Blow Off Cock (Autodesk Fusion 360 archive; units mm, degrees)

design "Blow Off Cock" references "Stud", "Cock", "Nut", "Gland", "Body"
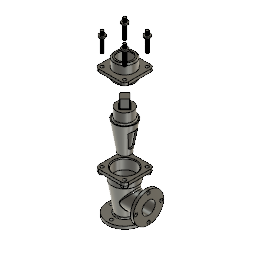
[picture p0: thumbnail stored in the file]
component_insert "Component Insert1"
ground "Ground1"
component_insert "Component Insert2"
joint "Assemble1" OffsetX 0 OffsetY 0 OffsetZ 0 AngleZ 0 OffsetX 0 OffsetY 0 OffsetZ 0 AngleZ 0 alignAngle 0 alignOffsetX 0 alignOffsetY 0 alignOffsetZ 0
component_insert "Component Insert3"
joint "Assemble2" OffsetX 0 OffsetY 0 OffsetZ 0 AngleZ 0 OffsetX 0 OffsetY 0 OffsetZ 0 AngleZ 0 alignAngle 0 alignOffsetX 0 alignOffsetY 0 alignOffsetZ 0
component_insert "Component Insert4"
joint "Assemble3" OffsetX 0 OffsetY 0 OffsetZ 0 AngleZ 0 OffsetX 0 OffsetY 0 OffsetZ 0 AngleZ 0 alignAngle 0 alignOffsetX 0 alignOffsetY 0 alignOffsetZ 0
component_insert "Component Insert5"
joint "Assemble4" OffsetX 0 OffsetY 0 OffsetZ 0 AngleZ 0 OffsetX 0 OffsetY 0 OffsetZ 0 AngleZ 0 alignAngle 0 alignOffsetX 0 alignOffsetY 0 alignOffsetZ 0
component_insert "Component Insert6"
joint "Assemble5" OffsetX 0 OffsetY 0 OffsetZ 0 AngleZ 0 OffsetX 0 OffsetY 0 OffsetZ 0 AngleZ 0 alignAngle 0 alignOffsetX 0 alignOffsetY 0 alignOffsetZ 0
component_insert "Component Insert7"
joint "Assemble6" OffsetX 0 OffsetY 0 OffsetZ 0 AngleZ 0 OffsetX 0 OffsetY 0 OffsetZ 0 AngleZ 0 alignAngle 0 alignOffsetX 0 alignOffsetY 0 alignOffsetZ 0
component_insert "Component Insert8"
joint "Assemble7" OffsetX 0 OffsetY 0 OffsetZ 0 AngleZ 0 OffsetX 0 OffsetY 0 OffsetZ 0 AngleZ 0 alignAngle 0 alignOffsetX 0 alignOffsetY 0 alignOffsetZ 0
component_insert "Component Insert9"
joint "Assemble8" OffsetX 0 OffsetY 0 OffsetZ 0 AngleZ 0 OffsetX 0 OffsetY 0 OffsetZ 0 AngleZ 0 alignAngle 0 alignOffsetX 0 alignOffsetY 0 alignOffsetZ 0
component_insert "Component Insert10"
joint "Assemble9" OffsetX 0 OffsetY 0 OffsetZ 0 AngleZ 0 OffsetX 0 OffsetY 0 OffsetZ 0 AngleZ 0 alignAngle 0 alignOffsetX 0 alignOffsetY 0 alignOffsetZ 0
component_insert "Component Insert11"
joint "Assemble10" OffsetX 0 OffsetY 0 OffsetZ 0 AngleZ 0 OffsetX 0 OffsetY 0 OffsetZ 0 AngleZ 0 alignAngle 0 alignOffsetX 0 alignOffsetY 0 alignOffsetZ 0

design "Nut"
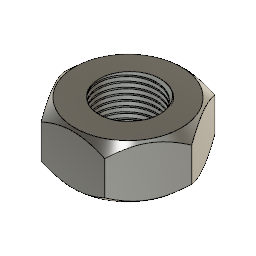
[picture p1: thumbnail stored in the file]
sketch "Sketch1" plane through (0, 0, 0) normal (0, 0, 1) x axis (1, 0, 0)
  line L1 (-12, 0) -> (-6, 10.3923)
  line L2 (-6, -10.3923) -> (-12, 0)
  line L3 (6, -10.3923) -> (-6, -10.3923)
  line L4 (12, 0) -> (6, -10.3923)
  line L5 (6, 10.3923) -> (12, 0)
  line L6 (-6, 10.3923) -> (6, 10.3923)
  circle C1 centre (0, 0) radius 6
  point P1 (0, 0)
  point P2 (0, 0)
  point P9 (0, 0)
  point P4 (-12, 0)
  point P7 (12, 0)
  point P3 (-6, 10.3923)
  point P8 (6, 10.3923)
  coincident P1 P2
  coincident P2 P9
  horizontal P4 P7
  dimension "d1" diameter C1 = 12
  dimension "d2" distance P3 P8 = 12
extrude "Extrude1" new body sketch "Sketch1" distance 10
sketch "Sketch2" plane through (0, 0, 5) normal (0, 0, 1) x axis (-1, 0, 0)
  line L1 (6, -10.3923) -> (-6, -10.3923)
  line L2 (12, 0) -> (6, -10.3923)
  line L3 (6, 10.3923) -> (12, 0)
  line L4 (-6, 10.3923) -> (6, 10.3923)
  line L5 (-12, 0) -> (-6, 10.3923)
  line L6 (-6, -10.3923) -> (-12, 0)
  circle C1 centre (0, 0) radius 6
  circle C2 centre (0, 0) radius 10
  point P1 (0, 0)
  point P9 (0, 0)
  coincident P1 P9
  dimension "d5" diameter C2 = 20
extrude "Extrude2" sketch "Sketch2" profile of C1 C2 no distance stored taper 48
mirror "Mirror1"
thread "Thread1"

design "Cock"
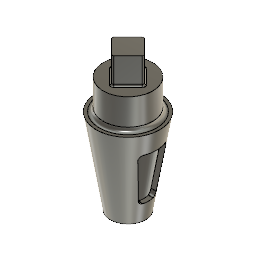
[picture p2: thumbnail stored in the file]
sketch "Sketch1" plane through (0, 0, 0) normal (0, 1, 0) x axis (1, 0, 0)
  line L1 (23, 0) -> (17, 0)
  line L2 (41, -110) -> (23, 0)
  line L3 (0, -144.3099) -> (0, 0)
  line L4 (17, 0) -> (34.0182, -104)
  line L5 (37.7698, 0) -> (0, 0)
  line L6 (32, -110) -> (41, -110)
  line L7 (32, -149) -> (32, -110)
  line L8 (26, -104) -> (34.0182, -104)
  line L9 (26, -143) -> (26, -104)
  line L10 (0, -149) -> (32, -149)
  line L11 (0, -143) -> (26, -143)
  line L12 (0, -143) -> (0, -149)
  point P1 (0, 0)
  point P4 (0, 0)
  point P8 (0, 0)
  point P7 (17, 0)
  point P14 (0, -149)
  point P15 (0, -143)
  point P3 (41, -110)
  horizontal L1
  coincident P1 P4
  perpendicular L1 L3
  parallel L2 L4
  coincident P1 P8
  perpendicular L3 L5
  horizontal P1 P7
  horizontal L6
  perpendicular L6 L7
  horizontal L8
  perpendicular L8 L9
  perpendicular L7 L10
  coincident L3 P14
  coincident L3 P15
  perpendicular L3 L11
  dimension "d1" = 46
  dimension "d2" = 34
  dimension "d3" distance L1 P3 = 110
  dimension "d4" = 82
  dimension "d5" distance L6 L8 = 6
  dimension "d7" = 64
  dimension "d8" distance L7 L9 = 6
  dimension "d9" distance L5 L10 = 149
  dimension "d10" distance L10 L11 = 6
revolve "Revolve1" sketch "Sketch1" AlongAngle 360
sketch "Sketch2" plane through (0, 0, 149) normal (0, 0, 1) x axis (-1, 0, 0)
  line L1 (21.2132, 0) -> (0, -21.2132)
  line L2 (0, 21.2132) -> (21.2132, 0)
  line L3 (-21.2132, 0) -> (0, 21.2132)
  line L4 (0, -21.2132) -> (-21.2132, 0)
  point P1 (0, 0)
  point P3 (21.2132, 0)
  point P5 (-21.2132, 0)
  point P2 (0, -21.2132)
  point P4 (0, 21.2132)
  perpendicular L2 L3
  horizontal P1 P3
  horizontal P1 P5
  vertical P1 P2
  vertical P1 P4
  equal L1 L2
  equal L1 L4
  dimension "d28" distance P2 P5 = 30
extrude "Extrude1" add sketch "Sketch2" along normal blind 34
fillet "Fillet1" radius 2
fillet "Fillet2" radius 2
fillet "Fillet3" radius 5
fillet "Fillet4" radius 5
sketch "Sketch5" plane through (0, 0, 0) normal (1, 0, 0) x axis (0, 1, 0)
  line L1 (-23, 0) -> (23, 0)
  line L2 (0, 97.021) -> (0, 0)
  line L3 (13.3134, 85) -> (-13.3134, 85)
  line L4 (11.5626, 27.3601) -> (18.2723, 79.3601)
  line L5 (-6.6037, 23) -> (6.6037, 23)
  line L6 (-18.2723, 79.3601) -> (-11.5626, 27.3601)
  line L7 (-41, 110) -> (41, 110)
  arc A1 centre (-13.3134, 80) radius 5 clockwise from (-18.2723, 79.3601) to (-13.3134, 85)
  arc A2 centre (13.3134, 80) radius 5 clockwise from (13.3134, 85) to (18.2723, 79.3601)
  arc A3 centre (6.6037, 28) radius 5 clockwise from (11.5626, 27.3601) to (6.6037, 23)
  arc A4 centre (-6.6037, 28) radius 5 clockwise from (-6.6037, 23) to (-11.5626, 27.3601)
  point P1 (0, 0)
  point P4 (0, 0)
  point P6 (-19, 85)
  point P7 (19, 85)
  point P8 (11, 23)
  point P9 (-11, 23)
  coincident P1 P4
  perpendicular L1 L2
  perpendicular L2 L3
  perpendicular L2 L5
  symmetric L2 P6 P7
  symmetric L2 P8 P9
  coincident P6 L6
  tangent L3 A1
  tangent L6 A1
  coincident P7 L4
  coincident P7 L3
  tangent L4 A2
  tangent L3 A2
  equal A1 A2
  coincident P8 L4
  tangent L4 A3
  tangent L5 A3
  equal A1 A3
  coincident P9 L5
  coincident P9 L6
  tangent L5 A4
  tangent L6 A4
  equal A1 A4
  dimension "d36" distance L3 L5 = 62
  dimension "d37" distance L3 L7 = 25
  dimension "d38" distance P6 P7 = 38
  dimension "d39" distance P8 P9 = 22
  dimension "d40" radius A1 = 5
extrude "Extrude4" cut sketch "Sketch5" profile of L3 L4 L5 L6 A1 A2 A3 A4 no distance stored
sketch "Sketch4" plane through (0, 0, 143) normal (0, 0, -1) x axis (1, 0, 0)
  circle C1 centre (0, 0) radius 26
  circle C2 centre (0, 0) radius 12
  point P1 (0, 0)
  point P3 (0, 0)
  coincident P1 P3
  dimension "d31" diameter C2 = 24
extrude "Extrude3" cut sketch "Sketch4" profile of C2 against normal blind 32
fillet "Fillet5" radius 5
fillet "Fillet6" radius 5

design "Gland"
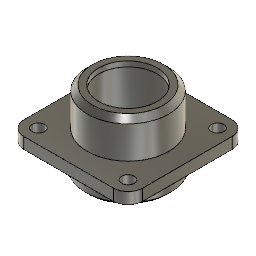
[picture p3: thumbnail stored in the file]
sketch "Sketch1" plane through (0, 0, 0) normal (0, 0, 1) x axis (1, 0, 0)
  circle C1 centre (0, 0) radius 41
  point P1 (0, 0)
  point P2 (0, 0)
  coincident P1 P2
  dimension "d1" diameter C1 = 82
extrude "Extrude1" new body sketch "Sketch1" along normal blind 25
sketch "Sketch2" plane through (0, 0, 25) normal (0, 0, 1) x axis (-1, 0, 0)
  line L1 (57, -57) -> (-57, -57)
  line L2 (57, 57) -> (57, -57)
  line L3 (-57, 57) -> (57, 57)
  line L4 (-57, -57) -> (-57, 57)
  line L5 (57, 57) -> (-57, -57)
  line L6 (-57, 57) -> (57, -57)
  circle C1 centre (0, 0) radius 41
  point P7 (0, 0)
  point P1 (0, 0)
  point P3 (-57, -57)
  point P4 (57, -57)
  point P5 (57, 57)
  horizontal L1
  perpendicular L1 L2
  parallel L1 L3
  parallel L2 L4
  coincident L5 P7
  coincident L6 P7
  coincident P1 P7
  dimension "d4" distance P3 P4 = 114
  dimension "d5" distance P4 P5 = 114
extrude "Extrude2" add sketch "Sketch2" profile of C1 L1 L2 L3 L4 along normal blind 11
fillet "Fillet1" sketch "Sketch5" radius 14
sketch "Sketch3" plane through (0, 0, 36) normal (0, 0, 1) x axis (-1, 0, 0)
  line L1 (43, -57) -> (-43, -57)
  line L2 (57, 43) -> (57, -43)
  line L3 (-43, 57) -> (43, 57)
  line L4 (-57, -43) -> (-57, 43)
  arc A1 centre (-43, -43) radius 14 clockwise from (-43, -57) to (-57, -43)
  arc A2 centre (43, -43) radius 14 clockwise from (57, -43) to (43, -57)
  arc A3 centre (43, 43) radius 14 clockwise from (43, 57) to (57, 43)
  arc A4 centre (-43, 43) radius 14 clockwise from (-57, 43) to (-43, 57)
  circle C1 centre (0, 0) radius 39
  point P1 (0, 0)
  point P14 (0, 0)
  coincident P1 P14
  dimension "d9" diameter C1 = 78
extrude "Extrude3" add sketch "Sketch3" profile of C1 along normal blind 36
chamfer "Chamfer1" distance 5 rotateAngle 45
sketch "Sketch4" plane through (0, 0, 0) normal (0, 1, 0) x axis (1, 0, 0)
  line L1 (-34, -72) -> (34, -72)
  line L2 (0, -90.6958) -> (0, 0)
  line L3 (-28, -72) -> (0, -72)
  line L4 (-28, -67) -> (-28, -72)
  line L5 (39, -67) -> (-39, -67)
  line L6 (-34, -67) -> (-28, -67)
  line L7 (-34, -21) -> (-34, -67)
  line L8 (-32, -21) -> (-34, -21)
  line L9 (41, 0) -> (-41, 0)
  line L10 (-32, 0) -> (-32, -21)
  line L11 (0, 0) -> (-32, 0)
  line L12 (0, -72) -> (0, 0)
  point P1 (0, 0)
  point P4 (0, 0)
  point P6 (0, -72)
  point P11 (-34, -67)
  point P16 (-32, 0)
  point P7 (-28, -72)
  point P17 (0, 0)
  point P18 (0, 0)
  point P8 (-28, -67)
  point P13 (-32, -21)
  coincident P1 P4
  perpendicular L1 L2
  coincident L2 P6
  perpendicular L2 L3
  perpendicular L3 L4
  coincident L5 P11
  perpendicular L4 L6
  perpendicular L5 L7
  perpendicular L7 L8
  coincident L9 P16
  perpendicular L5 L10
  coincident L1 P7
  coincident P1 P17
  coincident P1 P18
  dimension "d15" distance L2 L4 = 28
  dimension "d16" distance L1 P8 = 5
  dimension "d17" distance L2 L7 = 34
  dimension "d18" distance L2 L10 = 32
  dimension "d19" distance P13 P16 = 21
revolve "Revolve1" sketch "Sketch4" AlongAngle 360
sketch "Sketch5" plane through (0, 0, 36) normal (0, 0, 1) x axis (-1, 0, 0)
  line L1 (43, -57) -> (-43, -57)
  line L2 (57, 43) -> (57, -43)
  line L3 (-43, 57) -> (43, 57)
  line L4 (-57, -43) -> (-57, 43)
  circle C1 centre (0, 0) radius 39
  arc A1 centre (-43, -43) radius 14 clockwise from (-43, -57) to (-57, -43)
  arc A2 centre (43, -43) radius 14 clockwise from (57, -43) to (43, -57)
  arc A3 centre (43, 43) radius 14 clockwise from (43, 57) to (57, 43)
  arc A4 centre (-43, 43) radius 14 clockwise from (-57, 43) to (-43, 57)
  circle C2 centre (43, 43) radius 6
  concentric A3 C2
  dimension "d26" diameter C2 = 12
extrude "Extrude4" cut sketch "Sketch5" profile of C2 to an object
rectangular_pattern "R-Pattern1" uSpaceDistance 86 vSpaceDistance 86
chamfer "Chamfer2" distance 3 rotateAngle 45

design "Stud"
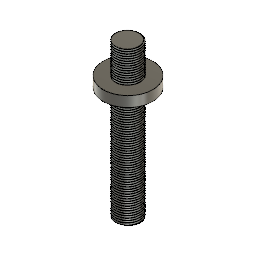
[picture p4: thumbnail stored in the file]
sketch "Sketch1" plane through (0, 0, 0) normal (0, 0, 1) x axis (1, 0, 0)
  circle C1 centre (0, 0) radius 6
  point P1 (0, 0)
  point P2 (0, 0)
  coincident P1 P2
  dimension "d1" diameter C1 = 12
extrude "Extrude1" new body sketch "Sketch1" along normal blind 54
sketch "Sketch2" plane through (0, 0, 54) normal (0, 0, 1) x axis (-1, 0, 0)
  circle C1 centre (0, 0) radius 6
  circle C2 centre (0, 0) radius 12
  point P1 (0, 0)
  point P3 (0, 0)
  coincident P1 P3
  dimension "d4" diameter C2 = 24
extrude "Extrude2" add sketch "Sketch2" along normal blind 5
sketch "Sketch3" plane through (0, 0, 59) normal (0, 0, 1) x axis (-1, 0, 0)
  circle C1 centre (0, 0) radius 12
  circle C2 centre (0, 0) radius 6
  point P1 (0, 0)
  point P3 (0, 0)
  coincident P1 P3
  dimension "d7" diameter C2 = 12
extrude "Extrude3" add sketch "Sketch3" profile of C2 along normal blind 15
thread "Thread1"
thread "Thread2"

design "Body"
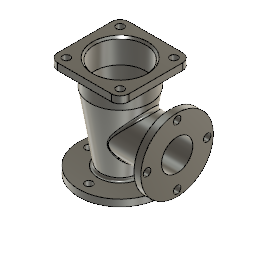
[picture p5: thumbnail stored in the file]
sketch "Sketch1" plane through (0, 0, 0) normal (0, 1, 0) x axis (1, 0, 0)
  line L1 (0, -187.0761) -> (0, 0)
  line L2 (30, -22) -> (30, 0)
  line L3 (17.5, 0) -> (30, 0)
  line L4 (17.5, -33) -> (17.5, 0)
  line L5 (66, -22) -> (30, -22)
  line L6 (66, -33) -> (66, -22)
  line L7 (30, -33) -> (66, -33)
  line L8 (48, -143) -> (30, -33)
  line L9 (48, -171) -> (48, -143)
  line L10 (41, -171) -> (48, -171)
  line L11 (41, -143) -> (41, -171)
  line L12 (23, -33) -> (41, -143)
  line L13 (23, -33) -> (17.5, -33)
  point P1 (0, 0)
  point P2 (0, 0)
  point P4 (30, 0)
  point P15 (23, -33)
  point P16 (23, -33)
  point P5 (30, -22)
  point P11 (48, -143)
  point P12 (48, -171)
  point P6 (17.5, 0)
  point P7 (17.5, -33)
  coincident P1 P2
  vertical L1
  parallel L1 L2
  horizontal P1 P4
  perpendicular L2 L3
  perpendicular L3 L4
  perpendicular L2 L5
  perpendicular L5 L6
  perpendicular L6 L7
  vertical L9
  perpendicular L9 L10
  perpendicular L10 L11
  equal L9 L11
  parallel L8 L12
  perpendicular L4 L13
  coincident P15 P16
  dimension "d1" = 60
  dimension "d2" = 35
  dimension "d3" distance P4 P5 = 22
  dimension "d5" = 132
  dimension "d7" = 60
  dimension "d8" = 96
  dimension "d9" distance L7 P11 = 110
  dimension "d10" distance P11 P12 = 28
  dimension "d11" = 82
  dimension "d12" distance L3 L7 = 33
  dimension "d13" distance P6 P7 = 33
revolve "Revolve1" sketch "Sketch1" AlongAngle 360
work_plane "WorkPlane1" AlongDistance 80
sketch "Sketch2" plane through (80, 0, 0) normal (1, 0, 0) x axis (0, 1, 0)
  circle C1 centre (0, 93) radius 36
  point P1 (0, 0)
  point P2 (0, 93)
  vertical P1 P2
  dimension "d16" diameter C1 = 72
  dimension "d17" distance P1 P2 = 93
extrude "Extrude1" add sketch "Sketch2" to an object
sketch "Sketch3" plane through (80, 0, 0) normal (1, 0, 0) x axis (0, 1, 0)
  circle C1 centre (0, 93) radius 36
  circle C2 centre (0, 93) radius 25
  concentric C1 C2
  dimension "d24" diameter C2 = 50
extrude "Extrude2" cut sketch "Sketch3" profile of C2 to an object
sketch "Sketch4" plane through (80, 0, 0) normal (1, 0, 0) x axis (0, 1, 0)
  circle C1 centre (0, 93) radius 25
  circle C2 centre (0, 93) radius 36
  circle C3 centre (0, 93) radius 25
  circle C4 centre (0, 93) radius 58
  concentric C1 C3
  concentric C1 C4
  equal C1 C3
  dimension "d25" diameter C4 = 116
extrude "Extrude3" add sketch "Sketch4" along normal blind 11
sketch "Sketch5" plane through (0, 0, 171) normal (0, 0, 1) x axis (-1, 0, 0)
  line L1 (57, -57) -> (-57, -57)
  line L2 (57, 57) -> (57, -57)
  line L3 (-57, 57) -> (57, 57)
  line L4 (-57, -57) -> (-57, 57)
  line L5 (57, 57) -> (-57, -57)
  line L6 (-57, 57) -> (57, -57)
  circle C1 centre (0, 0) radius 48
  circle C2 centre (0, 0) radius 41
  circle C3 centre (0, 0) radius 41
  point P7 (0, 0)
  point P1 (0, 0)
  point P8 (0, 0)
  point P4 (57, -57)
  point P5 (57, 57)
  point P3 (-57, -57)
  horizontal L1
  perpendicular L1 L2
  parallel L1 L3
  parallel L2 L4
  coincident L5 P7
  coincident L6 P7
  coincident P1 P7
  coincident P7 P8
  equal C2 C3
  dimension "d28" distance P4 P5 = 114
  dimension "d29" distance P3 P4 = 114
extrude "Extrude4" add sketch "Sketch5" profile of C1 C2 L1 L2 L3 L4 C3 along normal blind 11
fillet "Fillet1" radius 14
sketch "Sketch6" plane through (0, 0, 182) normal (0, 0, 1) x axis (-1, 0, 0)
  line L1 (43, -57) -> (-43, -57)
  line L2 (57, 43) -> (57, -43)
  line L3 (-43, 57) -> (43, 57)
  line L4 (-57, -43) -> (-57, 43)
  arc A1 centre (-43, -43) radius 14 clockwise from (-43, -57) to (-57, -43)
  arc A2 centre (43, -43) radius 14 clockwise from (57, -43) to (43, -57)
  arc A3 centre (43, 43) radius 14 clockwise from (43, 57) to (57, 43)
  arc A4 centre (-43, 43) radius 14 clockwise from (-57, 43) to (-43, 57)
  circle C1 centre (0, 0) radius 41
  circle C2 centre (43, 43) radius 6
  circle C3 centre (43, -43) radius 6
  circle C4 centre (-43, -43) radius 6
  circle C5 centre (-43, 43) radius 6
  concentric A3 C2
  concentric A2 C3
  concentric A1 C4
  concentric A4 C5
  equal C2 C3
  equal C3 C4
  equal C4 C5
  dimension "d33" diameter C2 = 12
extrude "Extrude5" cut sketch "Sketch6" profile of C2 C3 C4 C5 to an object
sketch "Sketch7" plane through (0, 0, 33) normal (0, 0, 1) x axis (-1, 0, 0)
  circle C1 centre (0, 0) radius 66
  circle C2 centre (0, 0) radius 30
  circle C3 centre (0, 50) radius 6
  point P1 (0, 0)
  point P3 (0, 50)
  vertical P1 P3
  dimension "d38" diameter C3 = 12
  dimension "d39" distance P1 P3 = 50
extrude "Extrude6" cut sketch "Sketch7" profile of C3 to an object
circular_pattern "C-Pattern1" TotalAngle 360
fillet "Fillet2" radius 4
chamfer "Chamfer1" distance 3 rotateAngle 45
sketch "Sketch9" plane through (91, 0, 0) normal (1, 0, 0) x axis (0, 1, 0)
  line L1 (-65.6451, 93) -> (0, 93)
  circle C1 centre (0, 93) radius 25
  circle C2 centre (0, 93) radius 58
  circle C3 centre (-48, 93) radius 6
  point P2 (0, 93)
  point P4 (0, 93)
  point P3 (-48, 93)
  coincident P2 P4
  horizontal L1
  coincident P3 L1
  dimension "d48" diameter C3 = 12
  dimension "d49" distance P3 P4 = 48
extrude "Extrude7" cut sketch "Sketch9" profile of C3 to an object
circular_pattern "C-Pattern2" TotalAngle 360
